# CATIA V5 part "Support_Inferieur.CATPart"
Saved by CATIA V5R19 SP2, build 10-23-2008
Part number: Support_Inferieur
Bounding box of the stored display mesh (mm): x 0 to 1, y -8 to 80.188, z -11.5 to 6.707
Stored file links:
  G:\EU_thinkMotion\CFAO_2010\MMS_groupe3\MMS_groupe3\A reprendre\lletoffe\lletoffe_Thinkmotion_CFAO\Modèle Catia\Support_Inferieur.CATPart
  E:\CFAO\Last Catia\Support inferieur.CATPart
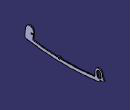
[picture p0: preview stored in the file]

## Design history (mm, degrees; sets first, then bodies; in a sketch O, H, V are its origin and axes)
Parameters
  Epaisseur = 1 mm
Set1
  Point1: (0, 30.2, -8.3)
  Point2: (1, 30.2, -8.3)
  Line1: type PtPt, FirstPoint Point1, SecondPoint Point2, Start 10, End 10
  Point3: (0, 0, 0)
  Point4: (1, 0, 0)
  Line2: type PtPt, FirstPoint Point3, SecondPoint Point4, Start 10, End 10
  Point5: (1, 74, 0)
  Point6: (0, 74, 0)
  Line3: type PtPt, FirstPoint Point5, SecondPoint Point6, Start 10, End 10
  Plane1: type Offset, RefPlane yz-plane, Offset 1 {= Epaisseur}
  Sketch1 on yz-plane, origin (0, 0, 0), H (0, 1, 0), V (0, 0, 1)
    circle A1 centre (0, 0) radius 1
    arc A2 centre (-2.6427, 2.2886) radius 4.5 from (1.7889, 1.5072) to (-7.0475, 3.2095) ccw
    arc A3 centre (37, -6) radius 45 from (-7.0475, 3.2095) to (-8, -6) ccw
    arc A4 centre (-6.25, -6) radius 1.75 from (-8, -6) to (-6.5549, -7.7232) ccw
    point P1 (-6.25, -6)
    circle A5 centre (30.2, -8.3) radius 1
    arc A6 centre (1.715, -4.6707) radius 1 from (0.7302, -4.497) to (1.5733, -5.6606) ccw
    line L1 (1.7889, 1.5072) -> (0.7302, -4.497)
    arc A7 centre (30.2, -8.3) radius 2 from (32.0474, -7.5339) to (28.3969, -7.4346) ccw
    construction line L2 through (-0.0438, 0) direction (1, 0)
    arc A8 centre (32.9712, -7.1508) radius 1 from (32.0474, -7.5339) to (32.955, -8.1507) ccw
    arc A9 centre (27.4954, -7.002) radius 1 from (27.4572, -8.0012) to (28.3969, -7.4346) ccw
    arc A10 centre (74, 0) radius 2 from (75.9696, 0.3473) to (72.0195, -0.2783) ccw
    arc A11 centre (68.9504, -5.1251) radius 1 from (69.0788, -6.1168) to (69.9504, -5.1251) ccw
    point P4 (69.9504, -5.1251)
    line L3 (69.9504, -5.1251) -> (69.9504, 0)
    line L4 (72.0195, -0.2783) -> (72.5548, -4.0877)
    line L5 (75.9696, 0.3473) -> (76.6376, -3.441)
    point P5 (-6.5549, -7.7232)
    point P6 (69.9504, -5.1251)
    arc A12 centre (37, 241.8166) radius 250 from (32.955, -8.1507) to (69.0788, -6.1168) ccw
    arc A13 centre (37, 238.4533) radius 249.9998 from (-6.5549, -7.7232) to (74.0988, -8.7786) ccw
    arc A14 centre (74, 0) radius 4.0496 from (78.0496, 0) to (69.9504, 0) ccw
    point P8 (78.0496, 0)
    point P9 (78.0496, 0)
    line L6 (78.0496, -1.5) -> (78.0496, 0)
    line L7 (79.1996, -6.5) -> (75.9504, -6.5)
    arc A15 centre (75.9504, -7.5) radius 1 from (75.9504, -6.5) to (74.9504, -7.5) ccw
    line L8 (74.9504, -7.5) -> (74.9504, -7.7896)
    point P10 (74.0988, -8.7786)
    point P11 (74.0988, -8.7786)
    arc A16 centre (73.9504, -7.7896) radius 1 from (74.0988, -8.7786) to (74.9504, -7.7896) ccw
    point P12 (74.0988, -8.7786)
    arc A17 centre (37, 241.8166) radius 250 from (1.5733, -5.6606) to (27.4572, -8.0012) ccw
    point P13 (37, -6)
    point P14 (-6.5549, -7.7232)
    point P15 (0, 0)
    point P17 (1.715, -4.6707)
    construction line L9 (0, -12.96) -> (0, -23.2752)
    reference projected point E1 (0, 0) from Line2
    reference projected point E2 (0, 0) from Line2
    reference projected point E3 (30.2, -8.3) from Line1
    reference projected point E4 (74, 0) from Line3
    axis line L10 (37, 241.8166) -> (37, 238.4533)
    arc A18 centre (79.1996, -5.5) radius 1 from (79.1996, -6.5) to (80.0465, -4.9682) ccw
    point P47 (79.1996, -5.5)
    point P48 (79.0496, -4.5)
    arc A19 centre (79.0496, -1.5) radius 1 from (78.0496, -1.5) to (78.2027, -2.0318) ccw
    point P49 (79.0496, -1.5)
    point P51 (78.2027, -2.0318)
    line L11 (78.2027, -2.0318) -> (80.0465, -4.9682)
    point P52 (78.2027, -2.0318)
    arc A20 centre (74.6019, -3.8) radius 2.0671 from (72.5548, -4.0877) to (76.6376, -3.441) ccw
    point P54 (74.6019, -3.8)
    radius A1 = 1
    radius A2 = 4.5
    radius A4 = 1.75
    radius A5 = 1
    radius A6 = 1
    distance A7 A5 = 1
    radius A8 = 1
    radius A9 = 1
    radius A10 = 2
    radius A11 = 1
    radius A15 = 1
    radius A16 = 1
    distance L8 L3 = 5
    angle L5 L6 = 10
    radius A3 = 45
    distance P15 L1 = 1.5
    angle L1 L9 = 10
    distance P1 L9 = 6.25
    distance P13 L9 = 37
    radius A13 = 249.9998
    radius A12 = 250
    distance P1 L2 = 6
    distance P17 L9 = 1.715
    radius A14 = 4.0496
    distance L7 L2 = 6.5
    distance L10 L9 = 37
    radius A19 = 1
    radius A18 = 1
    distance P49 L7 = 5
    distance P48 L7 = 2
    distance L6 P47 = 1.15
    angle L4 L6 = 8
    distance P54 L2 = 3.8
    tangency: A3 A2, A4 A3, L1 A6, L1 A2, A9 A7, A8 A7, L3 A11, L4 A10, L5 A10, A14 L3, A11 A12, L6 A14, A15 L7, L8 A15, A16 A13, A16 L8, A8 A12, A9 A17, A6 A17, A4 A13, A12 A17, A19 L6, A18 L7, A18 L11, L11 A19, L4 A20, A20 L5
    coincidence: P4 A11, A4 P5, L3 P6, P4 P6, P9 P8, P11 P10, P12 P11, P14 P5, P15 L2, E2 L9, P51 P52
    parallelism: L6 L8, L6 L3
    perpendicularity: L9 L2, L6 L2
    concentricity: A1 E1, E3 A5, E4 A10, A14 A10
    vertical: L9 V, L10 V
    horizontal: L7 H
Body1 (main body)
  Pad1: profile Sketch1, direction (1, 0, 0), up to Plane1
